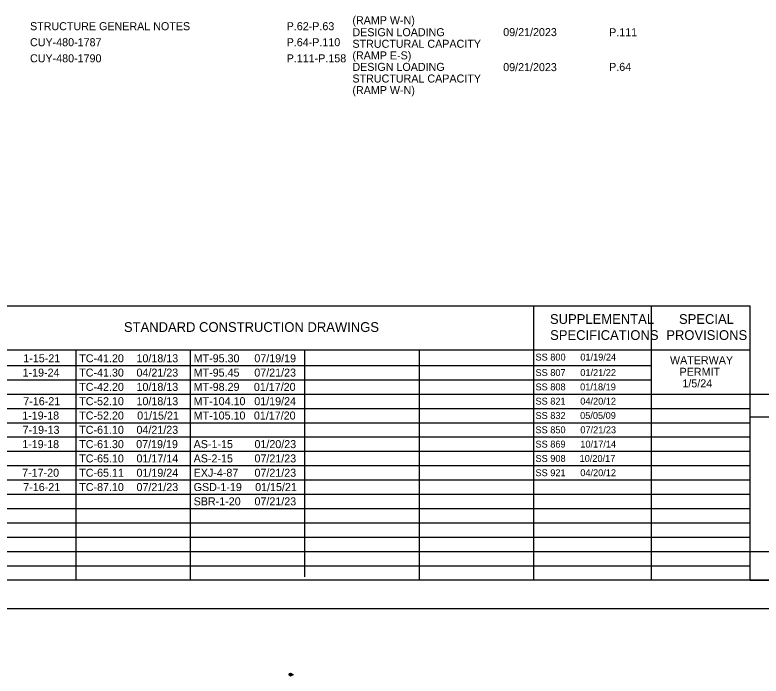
# Model space of a CAD drawing. Extents: x 0 to 34, y -1.2 to 22.
# Drawn here: x 12.18 to 25.22, y -1.18 to 10.38 of the extents above; entities that cross this region are included whole.
import ezdxf

# ---------------------------------------------------------------- set-up
doc = ezdxf.new("R2010")
doc.units = 0
for name, color, linetype in [('SH_Border', 7, 'Continuous'), ('SH_Cut_Line', 7, 'Continuous'), ('SH_Data', 7, 'Continuous')]:
    doc.layers.add(name, color=color, linetype=linetype)

msp = doc.modelspace()

# ---------------------------------------------------------------- linework, layer by layer
at = {"layer": 'SH_Border'}
msp.add_lwpolyline([(1.5, 21.5), (33.5, 21.5), (33.5, 0.5), (1.5, 0.5)], close=True, dxfattribs=at)
at = {"layer": 'SH_Cut_Line'}
for p, q in [((16.974, -1.152), (17.026, -1.152)), ((17, -1.152), (17.049, -1.152))]:
    msp.add_line(p, q, dxfattribs=at)
msp.add_lwpolyline([(0, 0), (34, 0), (34, 22), (0, 22)], close=True, dxfattribs=at)
msp.add_circle((17, -1.152), 0.026, dxfattribs=at)
at = {"layer": 'SH_Data'}
for p, q in [((11.25, 5.292), (25.034, 5.292)), ((21.25, 0.5), (21.25, 5.292)), ((23.309, 0.5), (23.309, 5.292)), ((25.034, 0.5), (25.034, 5.292)), ((11.25, 4.521), (25.034, 4.521)), ((13.25, 0.5), (13.25, 4.521)), ((15.25, 0.5), (15.25, 4.521)), ((17.25, 0.555), (17.25, 4.521)), ((19.25, 0.5), (19.25, 4.521)), ((11.25, 4.25), (23.309, 4.25)), ((11.25, 4), (23.309, 4)), ((11.25, 3.75), (25.034, 3.75)), ((25.034, 0.5), (25.034, 3.75)), ((25.034, 3.75), (27.834, 3.75)), ((11.25, 3.5), (25.034, 3.5)), ((25.034, 3.35), (27.834, 3.35)), ((11.25, 3.25), (25.034, 3.25)), ((11.25, 3), (25.034, 3)), ((11.25, 2.75), (25.034, 2.75)), ((11.25, 2.5), (25.034, 2.5)), ((11.25, 2.25), (25.034, 2.25)), ((11.25, 2), (25.034, 2)), ((11.25, 1.75), (25.034, 1.75)), ((11.25, 1.5), (25.034, 1.5)), ((11.25, 1.25), (25.034, 1.25)), ((11.25, 1), (25.034, 1)), ((11.25, 0.75), (25.034, 0.75)), ((25.034, 0.5), (27.834, 0.5))]:
    msp.add_line(p, q, dxfattribs=at)
msp.add_lwpolyline([(25.034, 0.5), (25.034, 1), (27.834, 1), (27.834, 0.5)], close=True, dxfattribs=at)

# ---------------------------------------------------------------- texts
at = {"layer": 'SH_Cut_Line'}
for s, height, p in [('STRUCTURE GENERAL NOTES', 0.14, (12.445, 10.108)), ('P.62-P.63', 0.14, (16.931, 10.108)), ('P.111', 0.14, (22.567, 10.003)), ('CUY-480-1787', 0.14, (12.445, 9.828)), ('P.64-P.110', 0.14, (16.931, 9.828)), ('CUY-480-1790', 0.14, (12.445, 9.547)), ('P.111-P.158', 0.14, (16.931, 9.547)), ('P.64', 0.14, (22.567, 9.397)), ('SUPPLEMENTAL', 0.17, (21.533, 4.976)), ('SPECIAL', 0.17, (23.788, 4.976)), ('STANDARD CONSTRUCTION DRAWINGS', 0.17, (14.086, 4.836)), ('SPECIFICATIONS', 0.17, (21.536, 4.696)), ('PROVISIONS', 0.17, (23.566, 4.696)), ('1-15-21', 0.14, (12.327, 4.305)), ('TC-41.20', 0.14, (13.305, 4.305)), ('10/18/13', 0.14, (14.306, 4.305)), ('MT-95.30', 0.14, (15.305, 4.305)), ('07/19/19', 0.14, (16.366, 4.305)), ('SS 800', 0.12, (21.28, 4.336)), ('01/19/24', 0.12, (22.064, 4.336)), ('WATERWAY ', 0.14, (23.631, 4.272)), ('1-19-24', 0.14, (12.315, 4.055)), ('TC-41.30', 0.14, (13.305, 4.055)), ('04/21/23', 0.14, (14.306, 4.055)), ('MT-95.45', 0.14, (15.305, 4.055)), ('07/21/23', 0.14, (16.365, 4.055)), ('SS 807', 0.12, (21.28, 4.065)), ('01/21/22', 0.12, (22.063, 4.065)), ('PERMIT', 0.14, (23.799, 4.069)), ('TC-42.20', 0.14, (13.305, 3.805)), ('10/18/13', 0.14, (14.306, 3.805)), ('MT-98.29', 0.14, (15.305, 3.805)), ('01/17/20', 0.14, (16.358, 3.805)), ('SS 808', 0.12, (21.28, 3.815)), ('01/18/19', 0.12, (22.06, 3.815)), ('1/5/24', 0.14, (23.848, 3.867)), ('7-16-21', 0.14, (12.327, 3.555)), ('TC-52.10', 0.14, (13.305, 3.555)), ('10/18/13', 0.14, (14.306, 3.555)), ('MT-104.10', 0.14, (15.305, 3.555)), ('01/19/24', 0.14, (16.365, 3.555)), ('SS 821', 0.12, (21.28, 3.565)), ('04/20/12', 0.12, (22.063, 3.565)), ('1-19-18', 0.14, (12.308, 3.305)), ('TC-52.20', 0.14, (13.305, 3.305)), ('01/15/21', 0.14, (14.318, 3.305)), ('MT-105.10', 0.14, (15.305, 3.305)), ('01/17/20', 0.14, (16.358, 3.305)), ('SS 832', 0.12, (21.28, 3.315)), ('05/05/09', 0.12, (22.06, 3.315)), ('7-19-13', 0.14, (12.315, 3.055)), ('TC-61.10', 0.14, (13.305, 3.055)), ('04/21/23', 0.14, (14.306, 3.055)), ('SS 850', 0.12, (21.28, 3.065)), ('07/21/23', 0.12, (22.064, 3.065)), ('1-19-18', 0.14, (12.308, 2.805)), ('TC-61.30', 0.14, (13.305, 2.805)), ('07/19/19', 0.14, (14.301, 2.805)), ('AS-1-15', 0.14, (15.305, 2.805)), ('01/20/23', 0.14, (16.368, 2.805)), ('SS 869', 0.12, (21.28, 2.815)), ('10/17/14', 0.12, (22.064, 2.815)), ('TC-65.10', 0.14, (13.305, 2.555)), ('01/17/14', 0.14, (14.306, 2.555)), ('AS-2-15', 0.14, (15.305, 2.555)), ('07/21/23', 0.14, (16.368, 2.555)), ('SS 908', 0.12, (21.28, 2.565)), ('10/20/17', 0.12, (22.051, 2.565)), ('7-17-20', 0.14, (12.307, 2.305)), ('TC-65.11', 0.14, (13.305, 2.305)), ('01/19/24', 0.14, (14.306, 2.305)), ('EXJ-4-87', 0.14, (15.305, 2.305)), ('07/21/23', 0.14, (16.368, 2.305)), ('SS 921', 0.12, (21.28, 2.315)), ('04/20/12', 0.12, (22.063, 2.315)), ('7-16-21', 0.14, (12.327, 2.055)), ('TC-87.10', 0.14, (13.305, 2.055)), ('07/21/23', 0.14, (14.306, 2.055)), ('GSD-1-19', 0.14, (15.305, 2.055)), ('01/15/21', 0.14, (16.38, 2.055)), ('SBR-1-20', 0.14, (15.305, 1.805)), ('07/21/23', 0.14, (16.368, 1.805)), ('1', 0.00328, (16.999, -1.146)), ('1', 0.00328, (16.999, -1.162)), ('Drawing', 0.00328, (17.032, -1.146)), ('1:1', 0.00328, (17.032, -1.162))]:
    msp.add_text(s, height=height, dxfattribs=at).set_placement(p)
at = {"layer": 'SH_Data'}
for s, p in [('(RAMP W-N)', (18.08, 10.213)), ('DESIGN LOADING ', (18.08, 10.003)), ('09/21/2023', (20.716, 10.005)), ('STRUCTURAL CAPACITY', (18.08, 9.801)), ('(RAMP E-S)', (18.08, 9.598)), ('DESIGN LOADING', (18.08, 9.397)), ('09/21/2023', (20.716, 9.393)), ('STRUCTURAL CAPACITY', (18.08, 9.194)), ('(RAMP W-N)', (18.08, 8.992))]:
    msp.add_text(s, height=0.14, dxfattribs=at).set_placement(p)

doc.saveas('drawing.dxf')
